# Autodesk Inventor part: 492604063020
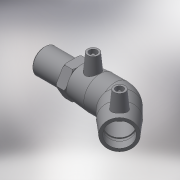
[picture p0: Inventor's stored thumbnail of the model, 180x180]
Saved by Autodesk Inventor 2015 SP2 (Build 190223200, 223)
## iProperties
Created: 2017-06
Part Number: 492604063020
Material: Generic
Description: PLASSON 45° ELBOW TRANSITION MALE 63-2"
Document SubType Name: Modeling
Designer: KIM
Mass: 500.504 g
Surface Area: 880.859 cm^2
Volume: 500.504 cm^3
Density: 1 g/cm^3
Appearance: Default
Author: KIM
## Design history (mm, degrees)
derived "492604.ipt"
feature "Solid1::492604.ipt"
tag "TaggingFeature1"
body "Solid1"
other parameters: "d2" = 82, "d4" = 37, "d5" = 73.8, "d8" = 168 deg, "d10" = 22.8, "d11" = 7.6, "d29" = 59, "d30" = 15, "d31" = 51.8, "d34" = 5 deg, "d41" = 4, "d42" = 14, "d43" = 0, "d49" = 63, "d50" = 40.95, "d51" = 22.8, "d52" = 58.71, "d54" = 135 deg, "d86" = 36.9, "d87" = 135 deg, "d88" = 148, "d90" = 57, "d91" = 0, "d92" = 57, "d93" = 0, "d101" = 3, "d102" = 0, "d107" = 0.1, "d108" = 48, "d109" = 59.614, "d110" = 41, "d111" = 10.25, "d112" = 82, "d113" = 41.7298, "d114" = 36.9, "d116" = 2.46, "d122" = 0, "d123" = 2.9807, "d_" = 63, "L_" = 189, "L_1" = 57, "D_" = 48, "A_" = 59, "d_2" = 12, "L_2" = 41, "R_" = 59.614, "D_1" = 82
